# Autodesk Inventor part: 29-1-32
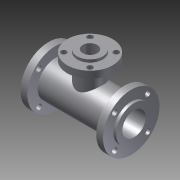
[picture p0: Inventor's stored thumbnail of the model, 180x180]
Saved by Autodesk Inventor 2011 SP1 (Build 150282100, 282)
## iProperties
Created: 2014-01
Part Number: 29-1-32
Document SubType Name: Modeling
Designer: Administrator
Density: 1 g/cm^3
Author: Administrator
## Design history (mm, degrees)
sketch "草图1"
  geometry: L1 (0, 0)-(0, 13); L2 (0, 13)-(2, 13); L3 (2, 13)-(2, 20.5); L4 (2, 20.5)-(7, 20.5); L5 (7, 20.5)-(7, 13); L6 (7, 13)-(57, 13); L7 (57, 13)-(57, 20.5); L8 (57, 20.5)-(62, 20.5); L9 (62, 20.5)-(62, 13); L10 (62, 13)-(64, 13); L11 (64, 13)-(64, 0); L12 (64, 0)-(0, 0)
  constraints: 24 end point, 5 parallel, 4 perpendicular, 2 point on line, 1 collinear, 1 vertical
  dimensions: "d0" = 13 distance of L1.start L1.end; "d1" = 2 distance of L1.end L2.end; "d2" = 7.5 distance of L2.end L3.end; "d3" = 5 distance of L3.end L4.end; "d4" = 50 distance of L5.end L6.end; "d5" = 5 distance of L7.end L8.end; "d6" = 2 distance of L9.end L10.end
revolve "旋转1" sketch "草图1" stored, may be unused: angle "d7" = 90 deg
hole "Hole1" diameter "d10" = 17; stored, may be unused: countersink angle "d14" = 90 deg, drill point angle "d16" = 118 deg; dims "d8" = 10, "d9" = 10, "d11" = 6, "d12" = 4, "d13" = 2, "d15" = 8
node "工作平面1"
sketch "草图2"
  geometry: C1 r 9.25 at (32, 0); 2 further points
  constraints: 1 centre point, 1 vertical alignment
  dimensions: "d18" = 18.5 diameter of C1
extrude "拉伸1" join sketch "草图2" stored distance "d19" = 10; taper "d20" = 0 deg
node "工作平面2"
sketch "草图3"
  geometry: C1 r 16.5 at (32, 0); 2 further points
  constraints: 1 centre point, 1 other
  dimensions: "d22" = 33 diameter of C1
extrude "拉伸2" join sketch "草图3" distance "d23" = 5; taper "d24" = 0 deg
hole "Hole2" diameter "d27" = 10.5; stored, may be unused: countersink angle "d31" = 90 deg, drill point angle "d33" = 118 deg; dims "d25" = 10, "d26" = 10, "d28" = 6, "d29" = 4, "d30" = 2, "d32" = 30
sketch "草图4"
  geometry: L1 (0, 0)-(24, 0); 2 further points
  constraints: 2 end point, 1 horizontal
hole "Hole3" sketch "草图4" at (-9.546, 9.546) diameter "d37" = 4; stored, may be unused: countersink angle "d41" = 90 deg, drill point angle "d43" = 118 deg; dims "d38" = 6, "d39" = 4, "d40" = 2, "d42" = 8
node "工作轴1"
pattern_circular "环形阵列1" dims angle "d45" = 360 deg
sketch "草图5"
  geometry: L1 (0, 0)-(24, 0); C1 r 20.5 at (0, 0) reference; 1 further point
  constraints: 2 end point, 1 coincident, 1 horizontal
hole "Hole4" sketch "草图5" at (-12.021, 12.021) diameter "d50" = 4; stored, may be unused: countersink angle "d54" = 90 deg, drill point angle "d56" = 118 deg; dims "d51" = 6, "d52" = 4, "d53" = 2, "d55" = 8
pattern_circular "环形阵列2" dims angle "d58" = 360 deg
node "实体1"
other parameters: "d17" = 31, "d21" = -2
